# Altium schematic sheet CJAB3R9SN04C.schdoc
size 127 x 101 mm
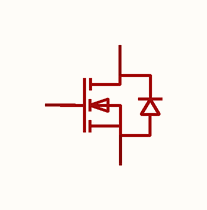
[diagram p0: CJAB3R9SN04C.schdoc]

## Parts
U?  cjab3r9sn04c  [PDFNWB-8_L3.3-W3.3-P0.65-BL-EP]  (value not drawn)

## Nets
NetU?_1: U?.1(S) U?.2(S) U?.3(S)
NetU?_5: U?.5(D) U?.6(D) U?.7(D) U?.8(D) U?.9(D)

Not connected (* = marked no-connect by the designer): U? 4(G)

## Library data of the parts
U? = cjab3r9sn04c: 数量:1个N沟道;漏源电压(Vdss):40V;连续漏极电流(Id):70A;导通电阻(RDS(on)):4.3mΩ@4.5V;耗散功率(Pd):50W;阈值电压(Vgs(th)):2.5V;; Manufacturer: CJ(江苏长电/长晶); AddInBom: yes; ModelId: da4e39fcb4454c0a86b16bc63c48b131; ModelName: PDFNWB-8_L3.3-W3.3-H0.8-P0.65-BL-EP; ModelTransform: 122.047,129.921,0,0,0,0,0,0.005,0; Number: 1个N沟道; Drain to Source Voltage: 40V; Current - Continuous Drain(Id): 70A; Pd - Power Dissipation: 50W; Gate Threshold Voltage (Vgs(th)): 2.5V; Gate Charge(Qg): 9nC@4.5V; Input Capacitance(Ciss): 1.2nF; Reverse Transfer Capacitance (Crss@Vds): 16pF; Output Capacitance(Coss): 430pF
